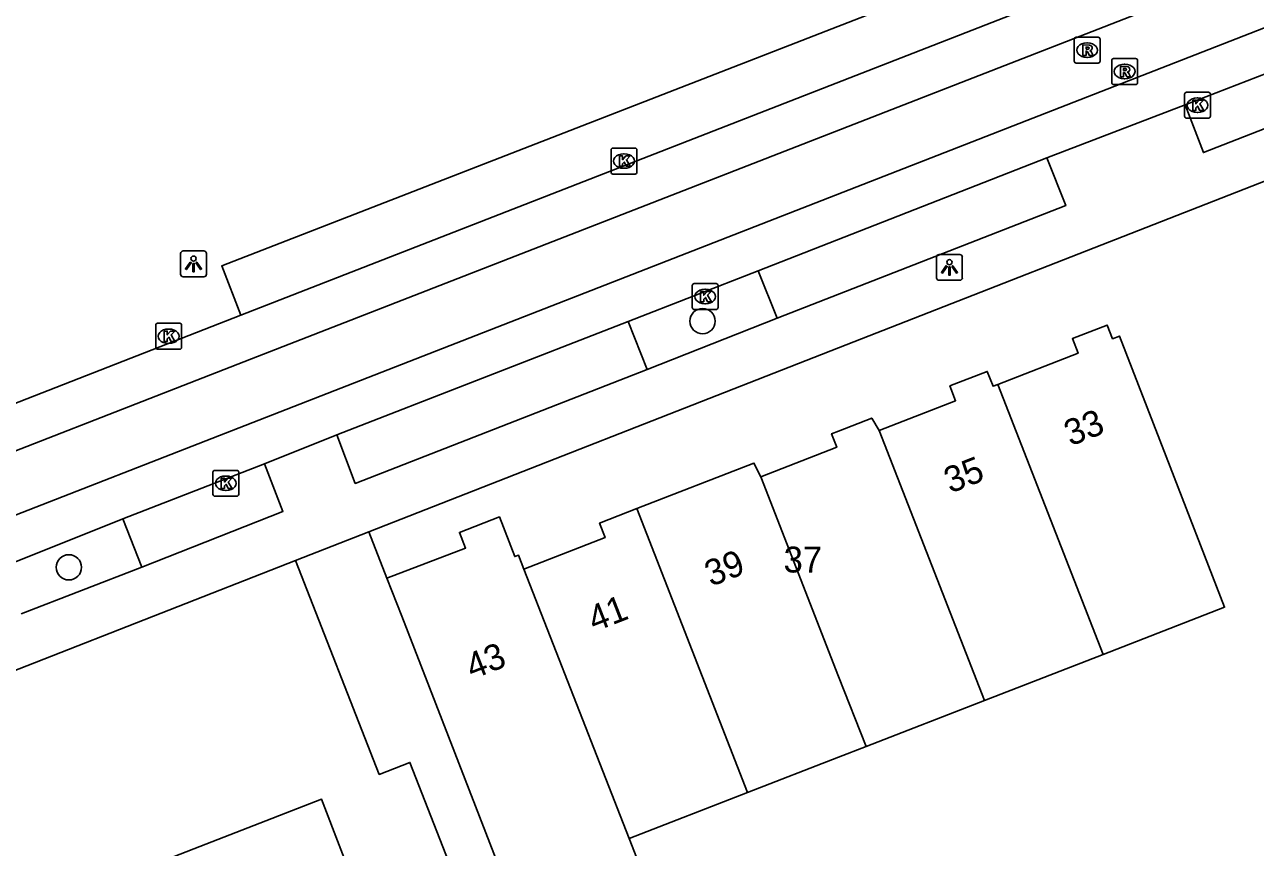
# Model space of a CAD drawing. Extents: x 159689 to 160786, y 387323 to 388339.
# Drawn here: x 159968.51 to 160016.12, y 387907.82 to 387939.62 of the extents above; entities that cross this region are included whole.
import ezdxf

# ---------------------------------------------------------------- set-up
doc = ezdxf.new("R2010")
doc.units = 0
for name, color, linetype in [('IMGEO_Boom', 7, 'Continuous'), ('IMGEO_Kolk', 7, 'Continuous'), ('IMGEO_Lichtpunt', 7, 'Continuous'), ('IMGEO_Pand', 7, 'Continuous'), ('IMGEO_Pand_nummerreeks', 7, 'Continuous'), ('IMGEO_Parkeervlak_open', 7, 'Continuous'), ('IMGEO_Rijbaan_lokaal_gesloten', 7, 'Continuous'), ('IMGEO_Rioolput', 7, 'Continuous'), ('IMGEO_Voetpad_open', 7, 'Continuous')]:
    doc.layers.add(name, color=color, linetype=linetype)

msp = doc.modelspace()

# ---------------------------------------------------------------- linework, layer by layer
at = {"layer": 'IMGEO_Boom'}
for centre in [(159994.737, 387928.16), (159970.226, 387918.645)]:
    msp.add_circle(centre, 0.489, dxfattribs=at)
at = {"layer": 'IMGEO_Kolk'}
for p, q in [((160013.376, 387936.079), (160013.376, 387936.931)), ((160013.451, 387937.005), (160014.303, 387937.005)), ((160013.864, 387936.785), (160013.889, 387936.785)), ((160014.377, 387936.931), (160014.377, 387936.079)), ((160013.887, 387936.225), (160013.862, 387936.225)), ((160014.303, 387936.005), (160013.451, 387936.005)), ((159991.196, 387933.92), (159991.196, 387934.772)), ((159991.271, 387934.846), (159992.123, 387934.846)), ((159992.197, 387934.772), (159992.197, 387933.92)), ((159991.684, 387934.626), (159991.709, 387934.626)), ((159992.123, 387933.846), (159991.271, 387933.846)), ((159991.707, 387934.066), (159991.682, 387934.066)), ((159994.337, 387928.684), (159994.337, 387929.536)), ((159994.412, 387929.61), (159995.264, 387929.61)), ((159995.338, 387929.536), (159995.338, 387928.684)), ((159994.825, 387929.39), (159994.85, 387929.39)), ((159995.264, 387928.61), (159994.412, 387928.61)), ((159994.848, 387928.83), (159994.823, 387928.83)), ((159973.66, 387928.076), (159974.512, 387928.076)), ((159973.585, 387927.15), (159973.585, 387928.002)), ((159974.073, 387927.856), (159974.098, 387927.856)), ((159974.586, 387928.002), (159974.586, 387927.15)), ((159974.096, 387927.296), (159974.071, 387927.296)), ((159974.512, 387927.076), (159973.66, 387927.076)), ((159975.872, 387922.393), (159976.724, 387922.393)), ((159975.797, 387921.467), (159975.797, 387922.319)), ((159976.285, 387922.173), (159976.31, 387922.173)), ((159976.798, 387922.319), (159976.798, 387921.467)), ((159976.724, 387921.393), (159975.872, 387921.393)), ((159976.308, 387921.613), (159976.283, 387921.613))]:
    msp.add_line(p, q, dxfattribs=at)
for points in [[(160013.376, 387936.079), (160013.376, 387936.931)], [(160013.451, 387937.005), (160014.303, 387937.005)], [(160013.697, 387936.705), (160013.82, 387936.705), (160013.82, 387936.554), (160013.95, 387936.705), (160014.114, 387936.705), (160013.968, 387936.554), (160014.121, 387936.305), (160013.969, 387936.305), (160013.884, 387936.469), (160013.82, 387936.402), (160013.82, 387936.305), (160013.697, 387936.305), (160013.697, 387936.705)], [(160014.377, 387936.931), (160014.377, 387936.079)], [(160014.303, 387936.005), (160013.451, 387936.005)], [(159991.196, 387933.92), (159991.196, 387934.772)], [(159991.271, 387934.846), (159992.123, 387934.846)], [(159992.197, 387934.772), (159992.197, 387933.92)], [(159991.517, 387934.546), (159991.64, 387934.546), (159991.64, 387934.395), (159991.77, 387934.546), (159991.934, 387934.546), (159991.788, 387934.395), (159991.941, 387934.146), (159991.789, 387934.146), (159991.704, 387934.31), (159991.64, 387934.243), (159991.64, 387934.146), (159991.517, 387934.146), (159991.517, 387934.546)], [(159992.123, 387933.846), (159991.271, 387933.846)], [(159994.337, 387928.684), (159994.337, 387929.536)], [(159994.412, 387929.61), (159995.264, 387929.61)], [(159995.338, 387929.536), (159995.338, 387928.684)], [(159994.658, 387929.31), (159994.781, 387929.31), (159994.781, 387929.159), (159994.911, 387929.31), (159995.075, 387929.31), (159994.929, 387929.159), (159995.082, 387928.91), (159994.93, 387928.91), (159994.845, 387929.074), (159994.781, 387929.007), (159994.781, 387928.91), (159994.658, 387928.91), (159994.658, 387929.31)], [(159995.264, 387928.61), (159994.412, 387928.61)], [(159973.66, 387928.076), (159974.512, 387928.076)], [(159973.585, 387927.15), (159973.585, 387928.002)], [(159973.906, 387927.776), (159974.029, 387927.776), (159974.029, 387927.625), (159974.159, 387927.776), (159974.323, 387927.776), (159974.177, 387927.625), (159974.33, 387927.376), (159974.178, 387927.376), (159974.093, 387927.54), (159974.029, 387927.473), (159974.029, 387927.376), (159973.906, 387927.376), (159973.906, 387927.776)], [(159974.586, 387928.002), (159974.586, 387927.15)], [(159974.512, 387927.076), (159973.66, 387927.076)], [(159975.872, 387922.393), (159976.724, 387922.393)], [(159975.797, 387921.467), (159975.797, 387922.319)], [(159976.118, 387922.093), (159976.241, 387922.093), (159976.241, 387921.942), (159976.371, 387922.093), (159976.535, 387922.093), (159976.389, 387921.942), (159976.542, 387921.693), (159976.39, 387921.693), (159976.305, 387921.857), (159976.241, 387921.79), (159976.241, 387921.693), (159976.118, 387921.693), (159976.118, 387922.093)], [(159976.798, 387922.319), (159976.798, 387921.467)], [(159976.724, 387921.393), (159975.872, 387921.393)]]:
    msp.add_lwpolyline(points, dxfattribs=at)
for centre, start, end in [((160013.453, 387936.929), 91.552, 178.448), ((160013.453, 387936.929), 91.552, 178.448), ((160014.301, 387936.929), 1.552, 88.448), ((160014.301, 387936.929), 1.552, 88.448), ((160013.453, 387936.081), 181.552, 268.448), ((160013.453, 387936.081), 181.552, 268.448), ((160014.301, 387936.081), 271.552, 358.448), ((160014.301, 387936.081), 271.552, 358.448), ((159991.273, 387934.77), 91.552, 178.448), ((159991.273, 387934.77), 91.552, 178.448), ((159992.121, 387934.77), 1.552, 88.448), ((159992.121, 387934.77), 1.552, 88.448), ((159991.273, 387933.922), 181.552, 268.448), ((159991.273, 387933.922), 181.552, 268.448), ((159992.121, 387933.922), 271.552, 358.448), ((159992.121, 387933.922), 271.552, 358.448), ((159994.414, 387929.534), 91.552, 178.448), ((159994.414, 387929.534), 91.552, 178.448), ((159995.262, 387929.534), 1.552, 88.448), ((159995.262, 387929.534), 1.552, 88.448), ((159994.414, 387928.686), 181.552, 268.448), ((159994.414, 387928.686), 181.552, 268.448), ((159995.262, 387928.686), 271.552, 358.448), ((159995.262, 387928.686), 271.552, 358.448), ((159973.662, 387928), 91.552, 178.448), ((159973.662, 387928), 91.552, 178.448), ((159974.51, 387928), 1.552, 88.448), ((159974.51, 387928), 1.552, 88.448), ((159973.662, 387927.152), 181.552, 268.448), ((159973.662, 387927.152), 181.552, 268.448), ((159974.51, 387927.152), 271.552, 358.448), ((159974.51, 387927.152), 271.552, 358.448), ((159975.874, 387922.317), 91.552, 178.448), ((159975.874, 387922.317), 91.552, 178.448), ((159976.722, 387922.317), 1.552, 88.448), ((159976.722, 387922.317), 1.552, 88.448), ((159975.874, 387921.469), 181.552, 268.448), ((159975.874, 387921.469), 181.552, 268.448), ((159976.722, 387921.469), 271.552, 358.448), ((159976.722, 387921.469), 271.552, 358.448)]:
    msp.add_arc(centre, 0.0765, start, end, dxfattribs=at)
for centre, major_axis, ratio, start_param, end_param in [((160013.863, 387936.505), (-0.387, 0.002), 0.722429, 4.712389, 7.853982), ((160013.888, 387936.505), (-0.39, 0.002), 0.717154, 1.570796, 4.712389), ((159991.683, 387934.346), (-0.387, 0.002), 0.722429, 4.712389, 7.853982), ((159991.708, 387934.346), (-0.39, 0.002), 0.717154, 1.570796, 4.712389), ((159994.824, 387929.11), (-0.387, 0.002), 0.722429, 4.712389, 7.853982), ((159994.849, 387929.11), (-0.39, 0.002), 0.717154, 1.570796, 4.712389), ((159974.072, 387927.576), (-0.387, 0.002), 0.722429, 4.712389, 7.853982), ((159974.097, 387927.576), (-0.39, 0.002), 0.717154, 1.570796, 4.712389), ((159976.284, 387921.893), (-0.387, 0.002), 0.722429, 4.712389, 7.853982), ((159976.309, 387921.893), (-0.39, 0.002), 0.717154, 1.570796, 4.712389)]:
    msp.add_ellipse(centre, major_axis=major_axis, ratio=ratio, start_param=start_param, end_param=end_param, dxfattribs=at)
at = {"layer": 'IMGEO_Lichtpunt'}
for p, q in [((159974.549, 387930.778), (159974.549, 387929.971)), ((159974.549, 387930.778), (159974.549, 387929.971)), ((159975.451, 387930.873), (159974.643, 387930.873)), ((159975.451, 387930.873), (159974.643, 387930.873)), ((159975.545, 387929.971), (159975.545, 387930.778)), ((159975.545, 387929.971), (159975.545, 387930.778)), ((160003.787, 387930.64), (160003.787, 387929.833)), ((160003.787, 387930.64), (160003.787, 387929.833)), ((160004.689, 387930.735), (160003.881, 387930.735)), ((160004.689, 387930.735), (160003.881, 387930.735)), ((160004.783, 387929.833), (160004.783, 387930.64)), ((160004.783, 387929.833), (160004.783, 387930.64)), ((159974.643, 387929.877), (159975.451, 387929.877)), ((159974.643, 387929.877), (159975.451, 387929.877)), ((160003.881, 387929.739), (160004.689, 387929.739)), ((160003.881, 387929.739), (160004.689, 387929.739))]:
    msp.add_line(p, q, dxfattribs=at)
for points in [[(159974.923, 387930.442), (159974.962, 387930.414), (159974.774, 387930.152), (159974.736, 387930.179), (159974.923, 387930.442)], [(159975.135, 387930.414), (159975.173, 387930.441), (159975.36, 387930.179), (159975.321, 387930.151), (159975.135, 387930.414)], [(159975.025, 387930.394), (159975.072, 387930.394), (159975.072, 387930.072), (159975.025, 387930.072), (159975.025, 387930.394)], [(160004.161, 387930.304), (160004.2, 387930.276), (160004.012, 387930.014), (160003.974, 387930.041), (160004.161, 387930.304)], [(160004.263, 387930.256), (160004.31, 387930.256), (160004.31, 387929.934), (160004.263, 387929.934), (160004.263, 387930.256)], [(160004.373, 387930.276), (160004.411, 387930.303), (160004.598, 387930.041), (160004.559, 387930.013), (160004.373, 387930.276)]]:
    msp.add_lwpolyline(points, dxfattribs=at)
for centre in [(159975.048, 387930.576), (160004.286, 387930.438)]:
    msp.add_circle(centre, 0.0994, dxfattribs=at)
for centre, start, end in [((159974.643, 387930.778), 90, 180), ((159974.643, 387930.778), 90, 180), ((159975.451, 387930.778), 0, 90), ((159975.451, 387930.778), 0, 90), ((160003.881, 387930.64), 90, 180), ((160003.881, 387930.64), 90, 180), ((160004.689, 387930.64), 0, 90), ((160004.689, 387930.64), 0, 90), ((159974.643, 387929.971), 180, 270), ((159974.643, 387929.971), 180, 270), ((159975.451, 387929.971), 270, 0), ((159975.451, 387929.971), 270, 360), ((160003.881, 387929.833), 180, 270), ((160003.881, 387929.833), 180, 270), ((160004.689, 387929.833), 270, 0), ((160004.689, 387929.833), 270, 360)]:
    msp.add_arc(centre, 0.0946, start, end, dxfattribs=at)
at = {"layer": 'IMGEO_Pand'}
for points in [[(160006.152, 387925.714), (160009.26, 387926.921), (160009.04, 387927.487), (160010.388, 387928.01), (160010.594, 387927.479), (160010.862, 387927.583), (160012.671, 387922.922), (160014.929, 387917.104), (160010.225, 387915.278)], [(160001.568, 387923.936), (160004.523, 387925.084), (160004.302, 387925.654), (160005.75, 387926.216), (160005.972, 387925.644), (160006.152, 387925.714)], [(160010.225, 387915.278), (160006.152, 387925.714)], [(159996.989, 387922.145), (159999.929, 387923.285), (159999.726, 387923.807), (160000, 387923.913), (160001.279, 387924.41), (160001.568, 387923.936)], [(160001.568, 387923.936), (160005.642, 387913.5)], [(159992.193, 387920.916), (159996.722, 387922.674), (159996.989, 387922.145)], [(160001.058, 387911.721), (160000, 387914.431), (159996.989, 387922.145)], [(159987.828, 387918.575), (159990.968, 387919.794), (159990.75, 387920.356), (159992.193, 387920.916)], [(159996.477, 387909.942), (159992.193, 387920.916)], [(159982.529, 387918.223), (159985.568, 387919.388), (159985.333, 387919.996), (159986.876, 387920.595), (159987.473, 387919.058), (159987.617, 387919.114), (159987.828, 387918.575)], [(159991.892, 387908.163), (159987.828, 387918.575)], [(159988.194, 387903.638), (159987.152, 387906.323), (159984.909, 387912.102), (159983.1, 387916.763), (159982.529, 387918.223)], [(160010.225, 387915.278), (160005.642, 387913.5)], [(160005.642, 387913.5), (160001.058, 387911.721)], [(160001.058, 387911.721), (160000, 387911.31), (159996.477, 387909.942)], [(159982.307, 387903.684), (159979.998, 387909.684), (159963.189, 387903.159), (159965.516, 387897.165)], [(159996.477, 387909.942), (159991.892, 387908.163)], [(159991.892, 387908.163), (159992.94, 387905.479), (159992.908, 387905.467), (159988.194, 387903.638)]]:
    msp.add_lwpolyline(points, dxfattribs=at)
at = {"layer": 'IMGEO_Parkeervlak_open'}
for points in [[(159976.881, 387928.393), (159976.14, 387930.3), (160037.196, 387954.02), (160037.945, 387952.192)], [(159996.89, 387930.101), (159997.625, 387928.272)], [(159992.592, 387926.294), (159991.862, 387928.146)], [(159972.31, 387920.523), (159973.042, 387918.654)]]:
    msp.add_lwpolyline(points, dxfattribs=at)
at = {"layer": 'IMGEO_Rijbaan_lokaal_gesloten'}
for points in [[(159976.881, 387928.393), (160037.945, 387952.192)], [(160041.859, 387951.835), (159977.527, 387926.791), (159949.223, 387915.763)], [(160042.67, 387949.729), (159950.038, 387913.604)], [(160013.407, 387936.521), (160024.591, 387940.857)], [(160013.407, 387936.521), (160008.058, 387934.469)], [(160008.058, 387934.469), (159996.89, 387930.101)], [(159991.862, 387928.146), (159996.89, 387930.101)], [(159948.604, 387917.346), (159976.881, 387928.393)], [(159991.862, 387928.146), (159980.592, 387923.765)], [(159980.592, 387923.765), (159977.786, 387922.643)], [(159977.786, 387922.643), (159972.31, 387920.523)], [(159967.652, 387918.655), (159972.31, 387920.523)]]:
    msp.add_lwpolyline(points, dxfattribs=at)
at = {"layer": 'IMGEO_Rioolput'}
for p, q in [((160009.11, 387938.207), (160009.11, 387939.059)), ((160009.185, 387939.133), (160010.037, 387939.133)), ((160010.111, 387939.059), (160010.111, 387938.207)), ((160009.598, 387938.913), (160009.623, 387938.913)), ((160010.037, 387938.133), (160009.185, 387938.133)), ((160009.621, 387938.353), (160009.596, 387938.353)), ((160010.56, 387937.38), (160010.56, 387938.232)), ((160010.635, 387938.306), (160011.487, 387938.306)), ((160011.048, 387938.086), (160011.073, 387938.086)), ((160011.561, 387938.232), (160011.561, 387937.38)), ((160011.487, 387937.306), (160010.635, 387937.306)), ((160011.071, 387937.526), (160011.046, 387937.526))]:
    msp.add_line(p, q, dxfattribs=at)
for points in [[(160009.11, 387938.207), (160009.11, 387939.059)], [(160009.185, 387939.133), (160010.037, 387939.133)], [(160010.111, 387939.059), (160010.111, 387938.207)], [(160009.699, 387938.831), (160009.447, 387938.833), (160009.447, 387938.433)], [(160009.447, 387938.433), (160009.571, 387938.433), (160009.571, 387938.595), (160009.582, 387938.595)], [(160009.625, 387938.752), (160009.571, 387938.752), (160009.571, 387938.671)], [(160009.571, 387938.671), (160009.623, 387938.671)], [(160009.629, 387938.566), (160009.7, 387938.433), (160009.84, 387938.433), (160009.775, 387938.559)], [(160010.037, 387938.133), (160009.185, 387938.133)], [(160010.56, 387937.38), (160010.56, 387938.232)], [(160010.635, 387938.306), (160011.487, 387938.306)], [(160011.561, 387938.232), (160011.561, 387937.38)], [(160011.149, 387938.004), (160010.897, 387938.006), (160010.897, 387937.606)], [(160010.897, 387937.606), (160011.021, 387937.606), (160011.021, 387937.768), (160011.032, 387937.768)], [(160011.075, 387937.925), (160011.021, 387937.925), (160011.021, 387937.844)], [(160011.021, 387937.844), (160011.073, 387937.844)], [(160011.079, 387937.739), (160011.15, 387937.606), (160011.29, 387937.606), (160011.225, 387937.732)], [(160011.487, 387937.306), (160010.635, 387937.306)]]:
    msp.add_lwpolyline(points, dxfattribs=at)
for centre, radius, start, end in [((160009.187, 387939.057), 0.0765, 91.552, 178.448), ((160009.187, 387939.057), 0.0765, 91.552, 178.448), ((160010.035, 387939.057), 0.0765, 1.552, 88.448), ((160010.035, 387939.057), 0.0765, 1.552, 88.448), ((160009.581, 387938.542), 0.0533, 26.0293, 88.6989), ((160009.607, 387938.86), 0.19, 274.7715, 282.9687), ((160009.631, 387938.656), 0.0964, 77.0061, 93.1865), ((160009.645, 387938.713), 0.0378, 276.6634, 79.6772), ((160009.698, 387938.721), 0.109, 350.3612, 89.416), ((160009.696, 387938.721), 0.112, 277.5842, 350.9817), ((160009.68, 387938.506), 0.108, 29.5134, 73.7905), ((160009.187, 387938.209), 0.0765, 181.552, 268.448), ((160009.187, 387938.209), 0.0765, 181.552, 268.448), ((160010.035, 387938.209), 0.0765, 271.552, 358.448), ((160010.035, 387938.209), 0.0765, 271.552, 358.448), ((160010.637, 387938.23), 0.0765, 91.552, 178.448), ((160010.637, 387938.23), 0.0765, 91.552, 178.448), ((160011.485, 387938.23), 0.0765, 1.552, 88.448), ((160011.485, 387938.23), 0.0765, 1.552, 88.448), ((160011.031, 387937.715), 0.0533, 26.0293, 88.6989), ((160011.057, 387938.033), 0.19, 274.7715, 282.9687), ((160011.081, 387937.829), 0.0964, 77.0061, 93.1865), ((160011.095, 387937.886), 0.0378, 276.6634, 79.6772), ((160011.148, 387937.894), 0.109, 350.3612, 89.416), ((160011.146, 387937.894), 0.112, 277.5842, 350.9817), ((160011.13, 387937.679), 0.108, 29.5134, 73.7905), ((160010.637, 387937.382), 0.0765, 181.552, 268.448), ((160010.637, 387937.382), 0.0765, 181.552, 268.448), ((160011.485, 387937.382), 0.0765, 271.552, 358.448), ((160011.485, 387937.382), 0.0765, 271.552, 358.448)]:
    msp.add_arc(centre, radius, start, end, dxfattribs=at)
for centre, major_axis, ratio, start_param, end_param in [((160009.597, 387938.633), (-0.387, 0.002), 0.722429, 4.712389, 7.853982), ((160009.622, 387938.633), (-0.39, 0.002), 0.717154, 1.570796, 4.712389), ((160011.047, 387937.806), (-0.387, 0.002), 0.722429, 4.712389, 7.853982), ((160011.072, 387937.806), (-0.39, 0.002), 0.717154, 1.570796, 4.712389)]:
    msp.add_ellipse(centre, major_axis=major_axis, ratio=ratio, start_param=start_param, end_param=end_param, dxfattribs=at)
at = {"layer": 'IMGEO_Voetpad_open'}
for points in [[(160045.29, 387944.846), (160000, 387927.125), (159981.828, 387920.015)], [(160025.316, 387939.042), (160014.109, 387934.677), (160013.407, 387936.521)], [(160008.058, 387934.469), (160008.784, 387932.623), (159997.625, 387928.272)], [(159997.625, 387928.272), (159992.592, 387926.294)], [(159992.592, 387926.294), (159981.305, 387921.886), (159980.592, 387923.765)], [(159977.786, 387922.643), (159978.506, 387920.808), (159973.042, 387918.654)], [(159981.828, 387920.015), (159978.996, 387918.907)], [(159982.529, 387918.223), (159981.828, 387920.015)], [(159958.196, 387910.768), (159978.996, 387918.907)], [(159973.042, 387918.654), (159968.386, 387916.85)], [(159978.996, 387918.907), (159982.232, 387910.638), (159983.417, 387911.102), (159991.235, 387891.12), (159999.652, 387869.965)]]:
    msp.add_lwpolyline(points, dxfattribs=at)

# ---------------------------------------------------------------- texts
at = {"layer": 'IMGEO_Pand_nummerreeks'}
for s, rotation, p in [('33', 21.4252, (160008.968, 387923.316)), ('35', 21.4252, (160004.321, 387921.492)), ('39', 21.2262, (159995.06, 387917.889)), ('41', 21.2262, (159990.548, 387916.137)), ('43', 21.2281, (159985.825, 387914.302))]:
    msp.add_text(s, height=1, rotation=rotation, dxfattribs=at).set_placement(p)
msp.add_text('37', height=1, dxfattribs=at).set_placement((159997.87, 387918.445))

doc.saveas('drawing.dxf')
